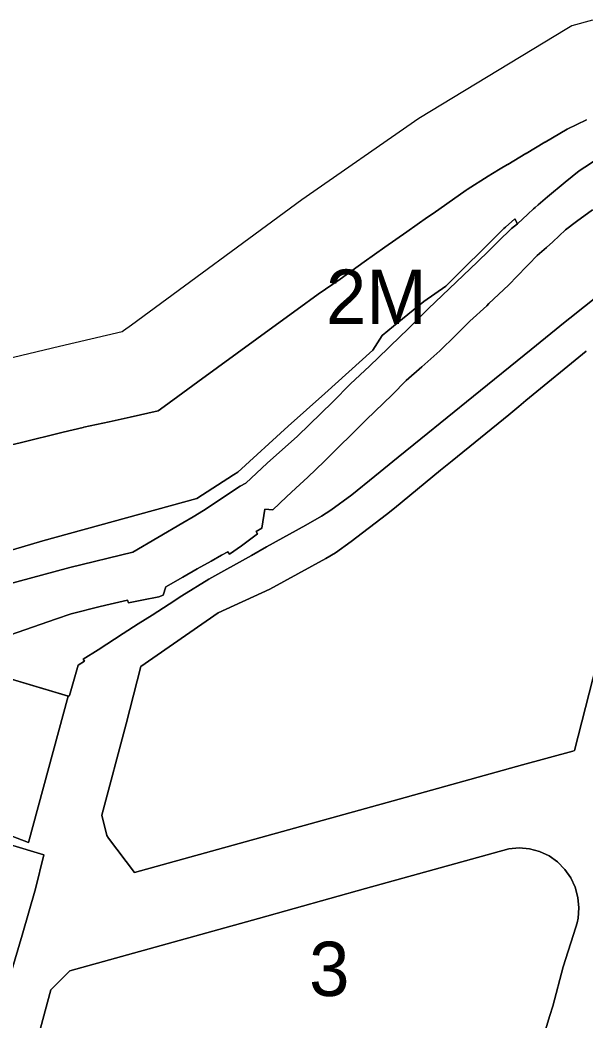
# Model space of a CAD drawing. Extents: x 598968 to 613553, y 4409678 to 4430833.
# Drawn here: x 608676.3 to 608801.6, y 4416183.2 to 4416404.6 of the extents above; entities that cross this region are included whole.
import ezdxf

# ---------------------------------------------------------------- set-up
doc = ezdxf.new("R2010")
doc.units = 0
for name, color, linetype in [('1', 7, 'Continuous'), ('ZONA 2M. CARRERS DE CASES. amb projecte especial', 7, 'Continuous'), ("ZONA 3. ILLES  D'EDIFICIS ENTRE MITGERES. EIXAMPLE.", 7, 'Continuous')]:
    doc.layers.add(name, color=color, linetype=linetype)

msp = doc.modelspace()

# ---------------------------------------------------------------- linework, layer by layer
at = {"layer": '1'}
for points in [[(608802.978, 4416404.5713), (608798.4481, 4416403.3012), (608797.345, 4416402.6334), (608764.5691, 4416382.7904), (608738.6897, 4416364.83), (608700.9607, 4416337.0894), (608699.2308, 4416335.8194), (608698.9409, 4416335.5994), (608685.0511, 4416332.399), (608649.192, 4416323.8178)], [(608671.1958, 4416309.8495), (608676.3158, 4416311.0796), (608685.8257, 4416313.3965), (608690.319, 4416314.4648), (608690.4588, 4416314.4957), (608696.0155, 4416315.7199), (608700.7155, 4416316.77), (608706.8654, 4416318.13), (608707.3708, 4416318.4888), (608711.2054, 4416321.2901), (608715.6453, 4416324.5301), (608733.1051, 4416337.2402), (608737.655, 4416340.5203), (608742.3091, 4416343.9228), (608747.1449, 4416347.2903), (608752.5048, 4416351.0804), (608757.0747, 4416354.3004), (608761.9247, 4416357.7205), (608766.5165, 4416360.9612), (608767.7227, 4416361.8123), (608770.7732, 4416363.9465), (608775.0245, 4416366.9206), (608775.2745, 4416367.0706), (608779.9144, 4416370.0406), (608780.8547, 4416370.6043), (608782.5781, 4416371.6286), (608784.2205, 4416372.6046), (608784.2644, 4416372.6306), (608788.2931, 4416375.0281), (608788.3144, 4416375.0407), (608792.4942, 4416377.5207), (608792.5005, 4416377.5245), (608797.4142, 4416380.4308), (608801.6541, 4416382.5208)], [(608805.1778, 4416374.5397), (608801.3242, 4416372.0609), (608800.0276, 4416371.235), (608796.9342, 4416368.6809), (608793.0743, 4416365.4309), (608791.0036, 4416363.6887), (608790.3343, 4416363.1209), (608789.96, 4416362.8016), (608788.7343, 4416361.6408), (608786.4344, 4416359.4808), (608785.0744, 4416358.4408), (608782.1344, 4416355.5809), (608780.1342, 4416353.6318), (608777.4545, 4416351.0208), (608766.7347, 4416340.7808), (608766.5347, 4416340.5908), (608762.3047, 4416336.3108), (608758.2648, 4416332.4508), (608757.8048, 4416332.0108), (608753.6248, 4416328.0507), (608749.4849, 4416324.1207), (608745.565, 4416320.1007), (608737.7051, 4416312.5606), (608731.0321, 4416306.5404), (608726.2952, 4416302.1206), (608725.0053, 4416301.4605), (608716.9354, 4416296.1105), (608714.6054, 4416294.7204), (608712.3154, 4416293.3304), (608701.2672, 4416286.8465), (608687.3411, 4416283.449), (608670.0953, 4416278.838)], [(608674.2358, 4416268.6001), (608684.1361, 4416272.0391), (608687.5958, 4416273.2402), (608694.0357, 4416274.8403), (608696.2557, 4416275.3604), (608700.1056, 4416276.2504), (608700.3456, 4416275.6604), (608703.2956, 4416276.2605), (608707.0155, 4416277.0205), (608708.0155, 4416277.3405), (608708.5655, 4416279.2405), (608712.3684, 4416281.3792), (608715.5381, 4416283.1618), (608718.5767, 4416284.8706), (608720.9116, 4416286.1838), (608722.2753, 4416286.9507), (608722.6953, 4416286.4407), (608725.3253, 4416288.2507), (608728.8552, 4416290.9207), (608728.5453, 4416291.4508), (608729.8452, 4416292.2107), (608730.5252, 4416296.3607), (608732.2552, 4416296.2707), (608735.3164, 4416299.1113), (608737.3851, 4416301.0308), (608739.984, 4416303.5005), (608743.625, 4416306.9608), (608752.9049, 4416316.1108), (608758.6648, 4416321.6709), (608761.8048, 4416324.8709), (608765.2347, 4416327.8809), (608769.2547, 4416331.4209), (608772.6646, 4416334.761), (608775.8446, 4416337.981), (608779.6145, 4416341.351), (608780.1045, 4416341.891), (608784.4244, 4416345.961), (608788.3805, 4416350.0419), (608788.9258, 4416350.6044), (608789.1957, 4416350.8828), (608790.4434, 4416352.17), (608790.7643, 4416352.501), (608792.8343, 4416354.241), (608794.2243, 4416355.521), (608797.0443, 4416358.131), (608799.5042, 4416360.0411), (608803.0042, 4416362.5911)], [(608803.0042, 4416362.5911), (608799.5042, 4416360.0411), (608797.0443, 4416358.131), (608794.2243, 4416355.521), (608792.8343, 4416354.241), (608790.7643, 4416352.501), (608790.4434, 4416352.17), (608789.1957, 4416350.8828), (608788.9258, 4416350.6044), (608788.3805, 4416350.0419), (608784.4244, 4416345.961), (608780.1045, 4416341.891), (608779.6145, 4416341.351), (608775.8446, 4416337.981), (608772.6646, 4416334.761), (608769.2547, 4416331.4209), (608765.2347, 4416327.8809), (608761.8048, 4416324.8709), (608758.6648, 4416321.6709), (608752.9049, 4416316.1108), (608743.625, 4416306.9608), (608739.984, 4416303.5005), (608737.3851, 4416301.0308), (608735.3164, 4416299.1113), (608732.2552, 4416296.2707), (608730.5252, 4416296.3607), (608729.8452, 4416292.2107), (608728.5453, 4416291.4508), (608728.8552, 4416290.9207), (608725.3253, 4416288.2507), (608722.6953, 4416286.4407), (608722.2753, 4416286.9507), (608720.9116, 4416286.1838), (608718.5767, 4416284.8706), (608715.5381, 4416283.1618), (608712.3684, 4416281.3792), (608708.5655, 4416279.2405), (608708.0155, 4416277.3405), (608707.0155, 4416277.0205), (608703.2956, 4416276.2605), (608700.3456, 4416275.6604), (608700.1056, 4416276.2504), (608696.2557, 4416275.3604), (608694.0357, 4416274.8403), (608687.5958, 4416273.2402), (608684.1361, 4416272.0391), (608674.2358, 4416268.6001)], [(608670.0953, 4416278.838), (608687.3411, 4416283.449), (608701.2672, 4416286.8465), (608712.3154, 4416293.3304), (608714.6054, 4416294.7204), (608716.9354, 4416296.1105), (608725.0053, 4416301.4605), (608726.2952, 4416302.1206), (608731.0321, 4416306.5404), (608737.7051, 4416312.5606), (608745.565, 4416320.1007), (608749.4849, 4416324.1207), (608753.6248, 4416328.0507), (608757.8048, 4416332.0108), (608758.2648, 4416332.4508), (608762.3047, 4416336.3108), (608766.5347, 4416340.5908), (608766.7347, 4416340.7808), (608777.4545, 4416351.0208), (608780.1342, 4416353.6318), (608782.1344, 4416355.5809), (608785.0744, 4416358.4408), (608786.4344, 4416359.4808), (608785.8044, 4416360.5809), (608783.7908, 4416358.7618), (608783.4244, 4416358.4308), (608782.8316, 4416357.8445), (608770.5646, 4416345.7107), (608765.6647, 4416342.2808), (608760.9458, 4416338.4607), (608758.9448, 4416336.8407), (608756.4748, 4416334.8007), (608754.4248, 4416331.5207), (608743.7526, 4416321.986), (608735.6651, 4416314.7606), (608724.5453, 4416304.6005), (608723.5302, 4416303.9449), (608715.4254, 4416298.7104), (608681.3658, 4416289.3799), (608666.6059, 4416285.0597)], [(608807.3942, 4416346.0814), (608797.9996, 4416338.6199), (608796.9943, 4416337.8213), (608789.4044, 4416331.7213), (608776.6646, 4416321.3512), (608765.0348, 4416311.9311), (608759.9848, 4416307.8511), (608754.8649, 4416303.681), (608749.745, 4416299.581), (608745.135, 4416296.131), (608743.0451, 4416294.8309), (608739.5451, 4416292.8809), (608730.8552, 4416288.0308), (608727.5053, 4416286.1608), (608718.1054, 4416280.9307), (608712.1255, 4416277.2106), (608709.3155, 4416275.4006), (608705.5256, 4416272.9706), (608702.4856, 4416271.0105), (608699.1657, 4416268.8805), (608693.6157, 4416265.3104), (608690.2977, 4416263.1774), (608690.5664, 4416262.7608), (608689.1858, 4416261.8704), (608687.2758, 4416255.1505), (608687.0258, 4416255.0405), (608666.686, 4416261.11), (608686.997, 4416255.0242), (608678.1952, 4416222.6561), (608658.2546, 4416230.2342)], [(608666.686, 4416261.11), (608687.0258, 4416255.0405), (608687.2758, 4416255.1505), (608689.1858, 4416261.8704), (608690.5664, 4416262.7608), (608690.2977, 4416263.1774), (608693.6157, 4416265.3104), (608699.1657, 4416268.8805), (608702.4856, 4416271.0105), (608705.5256, 4416272.9706), (608709.3155, 4416275.4006), (608712.1255, 4416277.2106), (608718.1054, 4416280.9307), (608727.5053, 4416286.1608), (608730.8552, 4416288.0308), (608739.5451, 4416292.8809), (608743.0451, 4416294.8309), (608745.135, 4416296.131), (608749.745, 4416299.581), (608754.8649, 4416303.681), (608759.9848, 4416307.8511), (608765.0348, 4416311.9311), (608776.6646, 4416321.3512), (608789.4044, 4416331.7213), (608796.9943, 4416337.8213), (608797.9996, 4416338.6199), (608807.3942, 4416346.0814)], [(608811.2247, 4416290.5886), (608799.0246, 4416242.9926), (608798.6788, 4416242.897), (608787.5376, 4416239.8151), (608758.888, 4416231.8903), (608701.6642, 4416216.0614), (608695.8974, 4416223.6564), (608695.5358, 4416224.201), (608694.4258, 4416228.6809), (608699.8157, 4416248.9408), (608703.0488, 4416261.596), (608720.1972, 4416273.4285), (608731.5716, 4416278.705), (608743.9827, 4416285.4785), (608746.1421, 4416286.7117), (608749.5909, 4416289.2151), (608757.4117, 4416295.1856), (608759.2111, 4416296.6409), (608769.3481, 4416305.012), (608771.9174, 4416307.0926), (608784.4745, 4416317.2614), (608786.7354, 4416319.1251), (608788.283, 4416320.4008), (608801.5753, 4416331.3586)], [(608801.5753, 4416331.3586), (608788.283, 4416320.4008), (608786.7354, 4416319.1251), (608784.4745, 4416317.2614), (608771.9174, 4416307.0926), (608769.3481, 4416305.012), (608759.2111, 4416296.6409), (608757.4117, 4416295.1856), (608749.5909, 4416289.2151), (608746.1421, 4416286.7117), (608743.9827, 4416285.4785), (608731.5716, 4416278.705), (608720.1972, 4416273.4285), (608703.0488, 4416261.596), (608699.8157, 4416248.9408), (608694.4258, 4416228.6809), (608695.5358, 4416224.201), (608695.8974, 4416223.6564), (608701.6642, 4416216.0614), (608758.888, 4416231.8903), (608787.5376, 4416239.8151), (608798.6788, 4416242.897), (608799.0246, 4416242.9926), (608811.2247, 4416290.5886)], [(608680.8542, 4416181.6055), (608683.1061, 4416190.1012), (608687.346, 4416194.2512), (608729.1205, 4416205.8768), (608752.7652, 4416212.4671), (608784.5048, 4416221.2926), (608786.801, 4416221.4817), (608789.0953, 4416221.2706), (608791.3184, 4416220.6658), (608793.4033, 4416219.6854), (608795.2872, 4416218.359), (608796.9132, 4416216.7268), (608798.2322, 4416214.8377), (608799.2044, 4416212.7491), (608799.8006, 4416210.5235), (608800.0027, 4416208.2285), (608799.8047, 4416205.9331), (608799.6247, 4416204.9031), (608799.3247, 4416203.9431), (608796.5447, 4416195.1531), (608794.2148, 4416186.4332), (608793.5998, 4416184.3982), (608784.975, 4416155.9534)]]:
    msp.add_lwpolyline(points, dxfattribs=at)
for points in [[(608666.686, 4416261.11), (608666.356, 4416261.13), (608666.236, 4416260.99), (608664.756, 4416257.01), (608657.5861, 4416250.81), (608652.6062, 4416246.73), (608652.2862, 4416246.53), (608651.8462, 4416246.6799), (608649.9362, 4416249.1199), (608649.8762, 4416249.1299), (608649.6862, 4416249.1199), (608644.6475, 4416246.0372), (608643.9163, 4416245.5898), (608643.4963, 4416245.5998), (608642.1363, 4416245.9898), (608631.5064, 4416241.4896), (608633.5311, 4416236.8605), (608640.7852, 4416235.1712), (608658.2546, 4416230.2342), (608678.1952, 4416222.6561), (608686.997, 4416255.0242)], [(608674.2708, 4416193.7014), (608676.7462, 4416202.1607), (608679.7254, 4416212.4483), (608681.606, 4416219.9308), (608673.9421, 4416222.19), (608663.9571, 4416187.4257), (608671.5351, 4416185.3276)], [(608663.9571, 4416187.4257), (608673.9421, 4416222.19), (608681.606, 4416219.9308), (608679.7254, 4416212.4483), (608676.7462, 4416202.1607), (608674.2708, 4416193.7014), (608671.5351, 4416185.3276)]]:
    msp.add_lwpolyline(points, close=True, dxfattribs=at)
at = {"layer": 'ZONA 2M. CARRERS DE CASES. amb projecte especial'}
for points in [[(608801.6541, 4416382.5208), (608797.4142, 4416380.4308), (608792.5005, 4416377.5245), (608792.4942, 4416377.5207), (608788.3144, 4416375.0407), (608788.2931, 4416375.0281), (608784.2644, 4416372.6306), (608784.2205, 4416372.6046), (608782.5781, 4416371.6286), (608780.8547, 4416370.6043), (608779.9144, 4416370.0406), (608775.2745, 4416367.0706), (608775.0245, 4416366.9206), (608770.7732, 4416363.9465), (608767.7227, 4416361.8123), (608766.5165, 4416360.9612), (608761.9247, 4416357.7205), (608757.0747, 4416354.3004), (608752.5048, 4416351.0804), (608747.1449, 4416347.2903), (608742.3091, 4416343.9228), (608737.655, 4416340.5203), (608733.1051, 4416337.2402), (608715.6453, 4416324.5301), (608711.2054, 4416321.2901), (608707.3708, 4416318.4888), (608706.8654, 4416318.13), (608700.7155, 4416316.77), (608696.0155, 4416315.7199), (608690.4588, 4416314.4957), (608690.319, 4416314.4648), (608685.8257, 4416313.3965), (608676.3158, 4416311.0796), (608671.1958, 4416309.8495)], [(608666.6059, 4416285.0597), (608681.3658, 4416289.3799), (608715.4254, 4416298.7104), (608723.5302, 4416303.9449), (608724.5453, 4416304.6005), (608735.6651, 4416314.7606), (608743.7526, 4416321.986), (608754.4248, 4416331.5207), (608756.4748, 4416334.8007), (608758.9448, 4416336.8407), (608760.9458, 4416338.4607), (608765.6647, 4416342.2808), (608770.5646, 4416345.7107), (608782.8316, 4416357.8445), (608783.4244, 4416358.4308), (608783.7908, 4416358.7618), (608785.8044, 4416360.5809), (608786.4344, 4416359.4808), (608788.7343, 4416361.6408), (608789.96, 4416362.8016), (608790.3343, 4416363.1209), (608791.0036, 4416363.6887), (608793.0743, 4416365.4309), (608796.9342, 4416368.6809), (608800.0276, 4416371.235), (608801.3242, 4416372.0609), (608805.1778, 4416374.5397)]]:
    msp.add_lwpolyline(points, dxfattribs=at)
at = {"layer": "ZONA 3. ILLES  D'EDIFICIS ENTRE MITGERES. EIXAMPLE."}
msp.add_lwpolyline([(608784.975, 4416155.9534), (608793.5998, 4416184.3982), (608794.2148, 4416186.4332), (608796.5447, 4416195.1531), (608799.3247, 4416203.9431), (608799.6247, 4416204.9031), (608799.8047, 4416205.9331), (608800.0027, 4416208.2285), (608799.8006, 4416210.5235), (608799.2044, 4416212.7491), (608798.2322, 4416214.8377), (608796.9132, 4416216.7268), (608795.2872, 4416218.359), (608793.4033, 4416219.6854), (608791.3184, 4416220.6658), (608789.0953, 4416221.2706), (608786.801, 4416221.4817), (608784.5048, 4416221.2926), (608752.7652, 4416212.4671), (608729.1205, 4416205.8768), (608687.346, 4416194.2512), (608683.1061, 4416190.1012), (608680.8542, 4416181.6055)], dxfattribs=at)

# ---------------------------------------------------------------- texts
at = {"layer": 'ZONA 2M. CARRERS DE CASES. amb projecte especial'}
msp.add_text('2M', height=12, dxfattribs=at).set_placement((608744.0098, 4416337.3704))
at = {"layer": "ZONA 3. ILLES  D'EDIFICIS ENTRE MITGERES. EIXAMPLE."}
msp.add_text('3', height=12, dxfattribs=at).set_placement((608740.2894, 4416188.7176))

doc.saveas('drawing.dxf')
